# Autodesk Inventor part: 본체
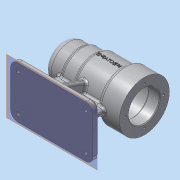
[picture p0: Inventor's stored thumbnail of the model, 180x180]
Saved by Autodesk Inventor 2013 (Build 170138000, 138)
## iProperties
Created: 2016-06
Part Number: 본체
Material: 알루미늄 6061
Document SubType Name: Modeling
Designer: dgall
Density: 2.71 g/cm^3
Mass: 671.069 g
Surface Area: 646.956 cm^2
Volume: 247.627 cm^3
Author: dgall
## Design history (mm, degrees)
sketch "스케치1"
  geometry: L1 (-56, 0)-(56, 0); L2 (56, 0)-(56, 34); L3 (56, 34)-(28, 34); L4 (28, 34)-(28, 30); L5 (28, 30)-(-11, 30); L6 (-11, 30)-(-11, 27); L7 (-11, 27)-(-31, 27); L8 (-31, 27)-(-31, 25); L9 (-31, 25)-(-56, 25); L10 (-56, 25)-(-56, 0); 2 further points
  constraints: 20 end point, 7 parallel, 2 perpendicular, 1 coincident, 1 horizontal, 1 midpoint
  dimensions: "d0" = 112 distance of L1.start L1.end; "d2" = 68 diameter of L3 L1; "d3" = 60 diameter of L5 L1; "d4" = 54 diameter of L7 L1; "d5" = 50 diameter of L9 L1; "d6" = 84 distance between parallel lines of L4 L10; "d7" = 45 distance between parallel lines of L6 L10; "d8" = 25 distance between parallel lines of L8 L10
revolve "회전1" sketch "스케치1" stored, may be unused: angle "d9" = 90 deg
sketch "스케치2"
  geometry: L1 (-50, 0)-(56, 0); L2 (56, -34)-(56, 34) reference; L3 (56, 21)-(41, 21); L4 (41, 21)-(41, 24); L5 (41, 24)-(-13, 24); L6 (-13, 24)-(-13, 21); L7 (-13, 21)-(-25, 21); L8 (-25, 21)-(-25, 17.5); L9 (-25, 17.5)-(-43, 17.5); L10 (-43, 17.5)-(-43, 16); L11 (-43, 16)-(-47, 16); L12 (-47, 16)-(-47, 10.5); L13 (-56, -25)-(-56, 25) reference; L14 (-47, 10.5)-(-50, 10.5); L15 (-50, 10.5)-(-50, 0); L16 (56, 21)-(56, 0); 2 further points
  constraints: 28 end point, 6 parallel, 6 perpendicular, 2 collinear, 2 point on line, 1 coincident, 1 horizontal, 1 midpoint
  dimensions: "d10" = 42 diameter of L3 L1; "d12" = 48 diameter of L5 L1; "d13" = 35 diameter of L9 L1; "d14" = 32 diameter of L11 L1; "d15" = 21 diameter of L14 L1; "d16" = 15 distance between parallel lines of L4 L2; "d17" = 54 distance between parallel lines of L6 L4; "d18" = 12 distance of L6.end L7.end; "d19" = 18 distance of L8.end L9.end; "d20" = 4 distance of L10.end L11.end; "d21" = 3 distance of L12.end L14.end
revolve "회전2" sketch "스케치2" stored, may be unused: angle "d22" = 90 deg
fillet "모깎기1" dims "d23" = 10
fillet "모깎기2" dims "d24" = 3
fillet "모깎기3" dims "d25" = 3
fillet "모깎기4" dims "d26" = 0.3
node "작업 평면1"
sketch "스케치3"
  geometry: L1 (-56, 34)-(-56, -34) reference; L2 (-56, -35)-(56, -35); L3 (56, -35)-(56, 35); L4 (56, 35)-(-56, 35); L5 (-56, -35)-(-56, 35); 2 further points
  constraints: 8 end point, 3 perpendicular, 2 point on line, 1 collinear, 1 horizontal alignment, 1 midpoint
  dimensions: "d28" = 112 distance of L2.start L2.end; "d30" = 70 distance of L2.end L3.end
extrude "돌출1" join sketch "스케치3" distance "d31" = 10; taper "d32" = 0 deg
sketch "스케치4"
  geometry: L1 (56, 35)-(-56, 35) reference; L2 (-56, 35)-(-56, -35) reference; L3 (-56, -35)-(56, -35) reference; L4 (56, -35)-(56, 35) reference; L5 (-36, 4)-(36, 4); L6 (36, 4)-(36, -4); L7 (36, -4)-(-36, -4); L8 (-36, -4)-(-36, 4); L9 (0, 35)-(0, -28.725); L10 (-56, 0)-(56, 0); 4 further points
  constraints: 12 end point, 6 midpoint, 5 perpendicular, 1 horizontal alignment, 1 parallel, 1 point on line
  dimensions: "d33" = 8 distance of L7.end L5.start; "d35" = 56 distance between parallel lines of L9 L4; "d36" = 72 distance of L5.start L5.end; "d37" = 35 distance between parallel lines of L10 L1
extrude "돌출2" join sketch "스케치4" stored distance "d38" = 0; taper "d39" = 0 deg
sketch "스케치5"
  geometry: L1 (-60, -35)-(-60, 35) reference; L2 (-60, 4)-(-24.678, 4) reference; L3 (-60, 28)-(-25.68, 15.509); L4 (-70, 35)-(-60, 35) reference; A1 r 30 centre (0, 0) between (-29.732, -4) and (-29.732, 4) reference; 1 further point
  constraints: 2 end point, 1 point on circle, 1 point on line
  dimensions: "d40" = 7 distance from line of L3.start L4; "d41" = 110 deg angle of L3 L1
extrude "돌출3" join sketch "스케치5" stored distance "d42" = 8; taper "d43" = 0 deg
fillet "모깎기5" dims "d44" = 3
fillet "모깎기6" dims "d45" = 3
fillet "모깎기7" dims "d46" = 3
fillet "모깎기8" dims "d47" = 3
fillet "모깎기9" dims "d48" = 10
hole "구멍1" diameter "d51" = 5; stored, may be unused: countersink angle "d55" = 90 deg, drill point angle "d57" = 118 deg; dims "d49" = 10, "d50" = 10, "d52" = 6, "d53" = 9, "d54" = 4, "d56" = 8
sketch "스케치6" dims "d59" = 52
  geometry: C1 r 21 at (0, 0) reference; C2 r 34 at (0, 0) reference; 2 further points
  constraints: 2 vertical alignment, 1 coincident, 2 other
hole "구멍2" sketch "스케치6" at (0, 26) diameter "d61" = 3.242; stored, may be unused: countersink angle "d65" = 90 deg, drill point angle "d67" = 118 deg; dims "d62" = 8, "d63" = 9, "d64" = 4, "d66" = 11
node "작업 평면2"
sketch "스케치7"
  geometry: L1 (47.5, -34)-(47.5, 34) reference; 2 further points
  constraints: 1 horizontal alignment, 1 other
  dimensions: "d71" = 48 distance from line of point (-0.5, 0) L1
feature "엠보싱1" sketch "스케치7" dims "d10" = 42, "d12" = 48, "d13" = 35, "d14" = 32, "d15" = 21, "d16" = 15, "d17" = 54, "d18" = 12, "d19" = 18, "d20" = 4, "d21" = 3, "d72" = 0.5, "d73" = 0
chamfer "모따기1" distance "d74" = 1; stored, may be unused: second distance "d75" = 2, angle "d76" = 45 deg
chamfer "모따기2" distance "d77" = 4; stored, may be unused: second distance "d78" = 2, angle "d79" = 45 deg
node "솔리드1"
mirror "대칭1"
mirror "대칭2"
mirror "대칭3"
pattern_circular "원형 패턴1" dims angle "d69" = 360 deg
